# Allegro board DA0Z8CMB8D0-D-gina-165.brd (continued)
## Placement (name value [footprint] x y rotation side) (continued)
HOLE7  *hg-c236d118p2  [HG-C236D118P2]  153.98 171.96 180 bottom
HOLE8  *hg-c236d118p2  [HG-C236D118P2]  145.78 171.46 180 bottom
HOLE9  *hg-c276d118p2  [HG-C276D118P2]  17.5 165.96 180 bottom
HOLE10  *hg-c236d118p2  [HG-C236D118P2]  89.78 157.96 180 bottom
HOLE11  *o-z8c-1  [O-Z8C-1]  230.64 148.36 180 bottom
HOLE12  *h-c217d138p2  [H-C217D138P2]  85.51 142 180 bottom
HOLE13  *hg-c236d118p2  [HG-C236D118P2]  247.2 133.46 180 bottom
HOLE14  *hg-c236d118p2  [HG-C236D118P2]  4.5 132.47 180 bottom
HOLE15  *h-c197d138p2  [H-C197D138P2]  3.5 125.47 180 bottom
HOLE16  *hg-c236d118p2  [HG-C236D118P2]  242.98 103.03 180 bottom
HOLE17  *hg-c276d118p2  [HG-C276D118P2]  188.7 97.46 180 bottom
HOLE18  *h-c236d165p2  [H-C236D165P2]  26.4 92.96 270 bottom
HOLE19  *h-tc197bc142d142p2  [H-TC197BC142D142P2]  194.11 81.96 180 bottom
HOLE20  *hg-c236d118p2  [HG-C236D118P2]  96.2 38.56 180 bottom
HOLE21  *hg-c276d118p2  [HG-C276D118P2]  246.88 26.46 180 bottom
J2  *jump  [JOPEN25X30_S]  127.77 67.07 180 top
JDIM1  ddr3-dimm1_h=5.2_std  [DDR-DS1SK-20401-STD-204P-SMT]  128.03 79.73 0 bottom
L2  blm15bb470sn1d  [RC0402]  103.84 160.64 0 top
L3  blm15bb470sn1d  [RC0402]  105.88 160.64 0 top
L4  blm15bb470sn1d  [RC0402]  107.91 160.64 0 top
L5  hcmc0805-371mfs/0.1a/370ohm  [CHOKE-WCM2012-4P]  138.77 158.48 180 top
L7  hcmc0805-371mfs/0.1a/370ohm  [CHOKE-WCM2012-4P]  138.77 156.32 180 top
L8  80ohm@100mhz  [RC0402]  107.91 155.18 270 top
L9  80ohm@100mhz  [RC0402]  108.8 148.32 270 top
L10  2.2uh/210ma_8  [RC0805]  141.82 143.62 180 top
L11  2.2uh/210ma_8  [RC0805]  141.82 141.59 180 top
L12  2.2uh/210ma_8  [RC0805]  137.5 140.83 90 top
L13  ev@pby160808t-300y-n  [RC0603]  28.28 138.29 270 top
L14  ev@hcb1005kf-181t15(180,1500ma)  [RC0402]  44.54 116.82 270 top
L15  ev@pby160808t-300y-n  [RC0603]  46.36 116.42 0 top
L16  2.2uh/210ma_8  [RC0805]  157.18 113.04 0 top
L17  4.7uh/680ma  [L2_5X1_8-1_8-SMT]  222.84 78.98 0 top
L18  blm11a05s/0.2a/120ohm_6  [RC0402]  140.67 71.23 270 top
L19  blm11a05s/0.2a/120ohm_6  [RC0402]  159.34 56.24 0 top
L20  blm11a05s/0.2a/120ohm_6  [RC0402]  158.84 53.96 0 top
L21  hcb2012kf220t60/6a/22ohm_8  [RC0805]  238.72 51.93 90 top
L23  hcmc0805-371mfs/0.1a/370ohm  [CHOKE-WCM2012-4P]  138.26 157.97 180 bottom
L25  80ohm@100mhz  [RC0402]  109.43 157.21 90 bottom
L26  hcmc0805-371mfs/0.1a/370ohm  [CHOKE-WCM2012-4P]  138.26 155.94 180 bottom
L27  80ohm@100mhz  [RC0402]  98 153.78 180 bottom
L28  80ohm@100mhz  [RC0402]  110.19 147.3 0 bottom
L29  80ohm@100mhz  [RC0402]  98.64 146.67 180 bottom
L30  2.2uh/210ma_8  [RC0805]  144.61 137.02 180 bottom
L31  *0_6  [RC0603]  92.67 50.4 90 bottom
L32  *short_6  [SHORT0603]  93.94 50.4 90 bottom
LED1  power led  [LED19-123-Y2ST1D-C30-2T-4P]  9.8 166.56 270 top
LED2  battery led  [LED19-123-Y2ST1D-C30-2T-4P]  26.3 166.56 270 top
NOREF  -  [unnamed]  30.95 44.43 0 top
NOREF#2  -  [#2]  66.53 163.08 0 top
NOREF#3  -  [#2]  77.81 114.92 0 top
NOREF#4  -  [unnamed]  235.24 150.9 0 top
NOREF#5  -  [#2]  47.77 -35.33 0 top
NOREF#6  -  [unnamed]  13.55 161.78 0 top
NOREF#7  -  [#2]  98.57 5.31 0 top
NOREF#8  -  [#2]  87.33 132.44 180 bottom
NOREF#9  -  [#2]  67.19 164.55 180 bottom
NOREF#10  -  [unnamed]  230.41 28.76 180 bottom
NOREF#11  -  [unnamed]  242.15 134.71 180 bottom
NOREF#12  -  [unnamed]  12.68 119.47 180 bottom
PAD1  *spad-e858x1268  [SPAD-E858X1268]  241.33 116.19 180 bottom
PC1  1500p/50v_4  [CC0402]  151.72 155.3 0 top
PC2  0.33u/6v_4  [CC0402]  147.41 154.92 0 top
PC3  2.2u/10v_4  [CC0402]  147.41 153.91 0 top
PC4  *100p/50v_4  [CC0402]  150.07 153.91 0 top
PC5  0.1u/50v_6  [CC0603]  135.82 151.93 90 top
PC6  1u/6.3v_4  [CC0402]  143.28 151.59 0 top
PC7  *0.1u/25v_4  [CC0402]  152.88 148.92 180 top
PC8  1000p/50v_6  [CC0603]  136.94 148.4 90 top
PC9  *0.1u/25v_4  [CC0402]  152.88 147.73 180 top
PC10  4700p/25v_4  [CC0402]  149.56 145.78 90 top
PC11  1000p/50v_4  [CC0402]  150.71 145.78 90 top
PC12  *ev@2.2n/50v_4  [CC0402]  22.95 141.46 90 top
PC13  *ev@1u/10v_4  [CC0402]  16.14 137.65 90 top
PC14  *ev@680p/50v_6  [CC0603]  11.24 133.9 270 top
PC15  ev@2200p/50v_6  [CC0603]  9.74 126.86 180 top
PC16  ev@4.7u/25v_8  [CC0805]  9.85 124.92 0 top
PC17  ev@0.1u/50v_6  [CC0603]  17.19 122.22 90 top
PC18  ev@1u/10v_4  [CC0402]  18.44 121.92 90 top
PC19  *ev@2.2n/50v_4  [CC0402]  26.12 117.2 0 top
PC20  *ev@1u/10v_4  [CC0402]  26.63 106.03 270 top
PC21  0.1u/50v_6  [CC0603]  30.29 103.82 180 top
PC22  2200p/50v_6  [CC0603]  30.26 102.47 180 top
PC23  ev@0.1u/10v_4  [CC0402]  41.46 99.2 0 top
PC24  0.1u/50v_6  [CC0603]  36.51 98.56 0 top
PC25  ev@10u/6.3v_6  [CC0603]  41.56 97.34 0 top
PC26  ev@10u/6.3v_6  [CC0603]  48.93 94.22 90 top
PC27  ev@1000p/50v_6  [CC0603]  45.65 94.17 180 top
PC28  ev@330u/2v_7343  [CC7343]  53.07 94.01 270 top
PC29  ev@330u/2v_7343  [CC7343]  62.29 93.56 270 top
PC30  ev@1000p/50v_6  [CC0603]  58.56 92.72 180 top
PC31  0.1u/50v_6  [CC0603]  31.71 90.53 90 top
PC32  ev@0.1u/50v_6  [CC0603]  63.59 87.08 90 top
PC33  ev@4.7u/25v_8  [CC0805]  65.36 87 90 top
PC34  ev@4.7u/25v_8  [CC0805]  61.78 86.95 90 top
PC35  0.1u/25v_4  [CC0402]  48.22 80.48 180 top
PC36  ev@0.22u/25v_6  [CC0603]  56.04 80.27 270 top
PC37  *680p/50v_6  [CC0603]  176.79 80.27 180 top
PC38  ev@0.1u/25v_4  [CC0402]  53.13 79.32 180 top
PC39  *ev@1u/10v_4  [CC0402]  67.88 79.05 90 top
PC40  ev@0.22u/25v_6  [CC0603]  49.67 79.05 0 top
PC41  1u/10v_4  [CC0402]  190.46 76.26 180 top
PC42  0.1u/50v_6  [CC0603]  190.25 74.96 180 top
PC43  0.1u/50v_6  [CC0603]  34.14 71.53 0 top
PC44  *ev@0.1u/25v_4  [CC0402]  57.47 70.89 270 top
PC45  ev@2700p/50v_4  [CC0402]  49.11 70.87 270 top
PC46  ev@33p/50v_4  [CC0402]  55.08 70.87 270 top
PC47  ev@1u/6.3v_4  [CC0402]  52.69 70.85 90 top
PC48  2200p/50v_6  [CC0603]  34.16 70.18 180 top
PC49  ev@4700p/25v_4  [CC0402]  54.7 69.17 180 top
PC50  4.7u/25v_8  [CC0805]  35.77 68.56 0 top
PC51  *680p/50v_6  [CC0603]  179.74 68.39 270 top
PC52  4.7u/6.3v_6  [CC0603]  199.09 68.36 180 top
PC53  0.1u/50v_6  [CC0603]  54.46 67.9 180 top
PC54  2200p/50v_6  [CC0603]  36.03 66.91 180 top
PC55  0.1u/50v_6  [CC0603]  52.9 66.58 0 top
PC56  0.1u/50v_6  [CC0603]  193.25 65.49 0 top
PC57  0.1u/50v_6  [CC0603]  201.63 65.31 0 top
PC58  0.47u/25v_6  [CC0603]  54.08 64.4 270 top
PC59  *47p/50v_4  [CC0402]  31.62 63.92 180 top
PC60  0.1u/50v_6  [CC0603]  203.64 63.89 270 top
PC61  0.1u/50v_6  [CC0603]  204.99 63.89 270 top
PC62  *47p/50v_4  [CC0402]  31.6 62.72 180 top
PC63  *680p/50v_6  [CC0603]  47.26 62.56 180 top
PC64  0.1u/25v_4  [CC0402]  195.54 61.45 180 top
PC65  10u/6.3v_6  [CC0603]  198.41 61.45 0 top
PC66  *680p/50v_6  [CC0603]  178.7 60.16 270 top
PC67  0.1u/10v_4  [CC0402]  198.76 59.39 270 top
PC68  0.22u/10v_4  [CC0402]  199.93 59.39 270 top
PC69  0.01u/25v_4  [CC0402]  195.39 59.34 270 top
PC70  0.1u/50v_6  [CC0603]  210.04 59.12 0 top
PC71  0.1u/50v_6  [CC0603]  204.96 57.16 270 top
PC72  1u/10v_4  [CC0402]  193.76 56.75 180 top
PC73  10u/6.3v_6  [CC0603]  201.94 56.14 180 top
PC74  0.1u/50v_6  [CC0603]  193.48 55.48 180 top
PC75  10u/6.3v_6  [CC0603]  201.94 54.87 180 top
PC76  *680p/50v_6  [CC0603]  206.21 54.04 90 top
PC77  0.1u/50v_6  [CC0603]  33.93 52.48 180 top
PC78  2200p/50v_6  [CC0603]  47.08 52.43 0 top
PC79  *100p/50v_4  [CC0402]  31.92 51.56 270 top
PC80  *330u/2v_7343  [CC7343]  171.81 50.66 270 top
PC81  1500p/50v_4  [CC0402]  132.94 49.38 270 top
PC82  *2200p/50v_4  [CC0402]  183.47 46.72 0 top
PC83  0.1u/25v_6  [CC0603]  132.51 43.99 0 top
PC84  *2.2n/50v_4  [CC0402]  206.1 41.77 270 top
PC85  1000p/50v_4  [CC0402]  132.63 41.63 270 top
PC86  22u/6.3v_8  [CC0805]  130.51 153.53 180 bottom
PC87  *330p/50v_4  [CC0402]  151.81 152.96 90 bottom
PC88  *0.01u/50v_4  [CC0402]  152.9 152.96 90 bottom
PC89  4.7u/25v_8  [CC0805]  137.92 152.53 90 bottom
PC90  2200p/50v_4  [CC0402]  136.36 152.51 90 bottom
PC91  0.1u/10v_4  [CC0402]  142.64 152.2 90 bottom
PC92  4.7u/25v_8  [CC0805]  134.07 152 180 bottom
PC93  0.22u/25v_6  [CC0603]  140.67 152 270 bottom
PC94  0.1u/10v_4  [CC0402]  130.06 151.77 180 bottom
PC95  0.12u/10v_4  [CC0402]  152.21 148.02 270 bottom
PC96  1u/10v_4  [CC0402]  141.06 144.89 180 bottom
PC97  ev@330u/2v_7343  [CC7343]  12.66 141.33 90 bottom
PC98  22u/6.3v_8  [CC0805]  128.99 141.21 180 bottom
PC99  *330u/2v_7343  [CC7343]  141.18 140.7 0 bottom
PC100  ev@0.1u/50v_6  [CC0603]  9.57 138.5 90 bottom
PC101  *ev@1u/10v_4  [CC0402]  16.34 115.17 180 bottom
PC102  0.1u/50v_6  [CC0603]  85.56 113.78 180 bottom
PC103  0.1u/50v_6  [CC0603]  93.68 110.85 270 bottom
PC104  ev@0.1u/10v_4  [CC0402]  50.38 100.69 270 bottom
PC105  33u/25v_6x4.5  [ECAP6_3X6_1-7_2]  176.36 100.44 270 bottom
PC106  ev@4.7u/25v_8  [CC0805]  41.97 93.91 90 bottom
PC107  ev@0.1u/50v_6  [CC0603]  39.2 93.43 90 bottom
PC108  ev@10u/25v_8  [CC0805]  62.32 82.03 90 bottom
PC109  ev@10u/25v_8  [CC0805]  67.4 85.84 180 bottom
PC110  330u/2.5v_6x4.2  [ECAP6_3X6_1-7_2]  174.68 83.96 180 bottom
PC111  ev@4.7u/25v_8  [CC0805]  39.56 83.32 180 bottom
PC112  ev@10u/25v_8  [CC0805]  39.56 81.09 0 bottom
PC113  0.1u/50v_6  [CC0603]  168.49 79.49 90 bottom
PC114  ev@33u/25v_6x4.5  [ECAP6_3X6_1-7_2]  66.23 78.04 90 bottom
PC115  ev@10u/25v_8  [CC0805]  44.33 77.56 180 bottom
PC116  *ev@2.2n/50v_4  [CC0402]  78.03 75.44 270 bottom
PC117  4.7u/25v_8  [CC0805]  184.82 74.84 270 bottom
PC118  2200p/50v_6  [CC0603]  186.57 74.69 90 bottom
PC119  *ev@0.1u/25v_4  [CC0402]  54.09 72.83 0 bottom
PC120  2200p/50v_6  [CC0603]  189.82 70.47 0 bottom
PC121  0.1u/50v_6  [CC0603]  52.73 68.7 90 bottom
PC122  4.7u/25v_8  [CC0805]  190.2 68.69 180 bottom
PC123  2200p/50v_6  [CC0603]  205.47 66.4 180 bottom
PC124  100p/50v_4  [CC0402]  59.79 65.98 0 bottom
PC125  47n/50v_6  [CC0603]  51.52 65.17 0 bottom
PC126  4.7u/25v_8  [CC0805]  205.19 64.8 0 bottom
PC127  220u/6.3v_6x4.2  [ECAP6_3X6_1-7_2]  170.5 62.57 0 bottom
PC128  0.1u/50v_6  [CC0603]  178.47 62.57 0 bottom
PC129  1u/16v_6  [CC0603]  51.53 62.46 0 bottom
PC130  0.01u/25v_4  [CC0402]  60.05 61.22 0 bottom
PC131  0.1u/25v_4  [CC0402]  55.58 60.05 90 bottom
PC132  0.1u/25v_4  [CC0402]  60.05 59.42 0 bottom
PC133  0.1u/25v_4  [CC0402]  57.5 58.12 0 bottom
PC134  10u/25v_1206  [CC1206]  55.97 55.86 180 bottom
PC135  10u/6.3v_6  [CC0603]  201.91 54.82 0 bottom
PC136  330u/2.5v_6x4.2  [ECAP6_3X6_1-7_2]  169.17 54.06 90 bottom
PC137  10u/25v_1206  [CC1206]  55.97 53.58 180 bottom
PC138  0.1u/50v_6  [CC0603]  173.59 52.99 270 bottom
PC139  4.7u/25v_8  [CC0805]  184.49 52.36 0 bottom
PC140  2200p/50v_4  [CC0402]  190.08 51.04 0 bottom
PC141  0.1u/50v_6  [CC0603]  204.86 50.83 180 bottom
PC142  *100p/50v_4  [CC0402]  134.18 49.41 90 bottom
PC143  0.01u/25v_4  [CC0402]  136.54 49.36 270 bottom
PC144  33u/25v_6x4.5  [ECAP6_3X6_1-7_2]  179.05 49.31 0 bottom
PC145  10u/6.3v_6  [CC0603]  129.74 47.17 270 bottom
PC146  220u/6.3v_6x4.2  [ECAP6_3X6_1-7_2]  206.26 46.49 0 bottom
PC147  0.1u/10v_4  [CC0402]  146.22 41.83 270 bottom
PC148  10u/6.3v_6  [CC0603]  148.91 41.76 90 bottom
PC149  10u/6.3v_6  [CC0603]  147.49 41.71 90 bottom
PC150  0.1u/50v_6  [CC0603]  134.84 41.12 180 bottom
PD1  1n4148ws  [DSM]  42.48 86.6 90 top
PD2  sbr1045sp5-13  [POWER-6_5-1_84-3P]  39.2 83.68 90 top
PD3  bzt52-b5v6s(5.6v)  [DSM]  31.33 68.69 180 top
PD4  bzt52-b5v6s(5.6v)  [DSM]  31.33 66.79 180 top
PD5  rb500v-40  [DSM]  51.39 62.59 270 top
PD6  1ps302  [UMT_213-3-1_3]  204.3 60.59 270 top
PD7  1ps302  [UMT_213-3-1_3]  207.2 60.16 270 top
PD8  da2j10100l  [DSM]  96.22 99.68 180 bottom
PD9  smaj20a  [D-DO-214AC]  27.62 97.8 180 bottom
PJ1  power conn  [20288-04XX-4P-L]  30.65 100.97 180 bottom
PJ2  50458-00801-v01  [50458-00801-V02-8P-L]  33.38 60.82 270 bottom
PL1  0.15uh_7x7x4  [CHOKE-PCMC063T-R82MN-4P-SMT]  132.29 145.9 180 bottom
PL2  ev@2.2uh_7x7x3  [CHOKE-PCMC063T-3R3MN-SMT]  13.34 132.53 0 bottom
PL3  ev@0.36uh_ldcr  [CHOKE-ETQP4LR36WFC-4P]  51.19 92.29 270 bottom
PL4  ev@0.36uh_ldcr  [CHOKE-ETQP4LR36WFC-4P]  62.67 92.14 270 bottom
PL5  2.2uh_7x7x3  [CHOKE-PCMC063T-3R3MN-SMT]  173.85 76.41 180 bottom
PL6  2.2uh_7x7x3  [CHOKE-PCMC063T-3R3MN-SMT]  179.16 66.91 180 bottom
PL7  6.8uh_7x7x3  [CHOKE-PCMC063T-3R3MN-SMT]  46.69 61.35 90 bottom
PL8  0.68uh_7x7x3  [CHOKE-PCMC063T-3R3MN-SMT]  181.06 57.39 180 bottom
PL9  2.2uh_7x7x3  [CHOKE-PCMC063T-3R3MN-SMT]  208.77 55.33 90 bottom
PL10  1uh_7x7x3  [CHOKE-PCMC063T-3R3MN-SMT]  140.99 43.99 0 bottom
PQ1  ev@pdtc143tt  [SOT23_213-3_3-2]  11.46 142.78 180 top
PQ2  ev@2n7002k  [SOT23_213-3_3-2]  15.71 140.57 180 top
PQ3  ev@2n7002k  [SOT23_213-3_3-2]  19.9 138.16 270 top
PQ4  ev@aon7408  [WDFN5-3_05X3_05-65]  24.09 138.16 90 top
PQ5  ev@ao3404  [SOT23_213-3_3-2]  25.23 114.66 270 top
PQ6  ev@2n7002k  [SOT23_213-3_3-2]  28.91 113.14 270 top
PQ7  ev@pdtc143tt  [SOT23_213-3_3-2]  27.9 109.08 270 top
PQ8  ev@2n7002k  [SOT23_213-3_3-2]  31.48 109.08 270 top
PQ9  aol1413  [SO-8FL-5P-OA]  38.62 92.29 180 top
PQ10  *ev@rjk03k5dpa  [SO-8FL-5P-OA]  78.52 89.57 90 top
PQ11  imd2at108  [IMD]  31.07 85.33 180 top
PQ12  ev@aon6414al  [SO-8FL-5P-OA]  63.05 81.98 180 top
PQ13  2n7002dw  [SC70-2_1-65-6P]  44.91 78.53 0 top
PQ14  *ev@pdtc143tt  [SOT23_213-3_3-2]  71.84 76.95 270 top
PQ15  ev@2n7002k  [SOT23_213-3_3-2]  59.96 72.49 90 top
PQ16  2n7002k  [SOT23_213-3_3-2]  175.47 71.18 0 top
PQ17  aon7410  [WDFN5-3_05X3_05-65]  39.95 69.93 0 top
PQ18  2n7002k  [SOT23_213-3_3-2]  59.18 67.94 0 top
PQ19  2n7002k  [SOT23_213-3_3-2]  175.29 67.24 0 top
PQ20  2n7002k  [SOT23_213-3_3-2]  35.12 64.13 180 top
PQ21  *2n7002k  [SOT23_213-3_3-2]  59.05 62.01 180 top
PQ22  aol1413  [SO-8FL-5P-OA]  38.97 56.54 90 top
PQ23  dtc144eu  [UMT_213-3-1_3]  180.63 51.42 90 top
PQ24  2n7002k  [SOT23_213-3_3-2]  209.25 49.64 180 top
PQ25  2n7002k  [SOT23_213-3_3-2]  180.3 47.74 180 top
PQ26  dtc144eu  [UMT_213-3-1_3]  205.9 47 90 top
PQ27  2n7002k  [SOT23_213-3_3-2]  209.38 45.83 180 top
PQ28  *2n7002k  [SOT23_213-3_3-2]  138.31 44.84 180 top
PQ29  2n7002k  [SOT23_213-3_3-2]  203.69 42.58 270 top
PQ30  ev@aon7752  [WDFN5-3_05X3_05-65]  16.91 125.26 270 bottom
PQ31  ev@aon7410  [WDFN5-3_05X3_05-65]  10.87 124.77 0 bottom
PQ32  aon7408  [WDFN5-3_05X3_05-65]  161.95 114.07 180 bottom
PQ33  2n7002k  [SOT23_213-3_3-2]  163.53 106.41 270 bottom
PQ34  2n7002k  [SOT23_213-3_3-2]  88.35 103.49 0 bottom
PQ35  2n7002k  [SOT23_213-3_3-2]  95.72 103.36 90 bottom
PQ36  ao3409  [SOT23_213-3_3-2]  99.4 103.36 270 bottom
PQ37  dtc144eu  [UMT_213-3-1_3]  102.7 102.6 270 bottom
PQ38  ev@aon6414al  [SO-8FL-5P-OA]  41.06 88.86 0 bottom
PQ39  ev@aon6752  [SO-8FL-5P-OA]  56.98 84.06 270 bottom
PQ40  ev@aon6752  [SO-8FL-5P-OA]  46.95 81.64 0 bottom
PQ41  aon7752  [WDFN5-3_05X3_05-65]  181.01 77.25 0 bottom
PQ42  *ev@2n7002k  [SOT23_213-3_3-2]  75.78 77.2 270 top
PQ43  *ev@2n7002k  [SOT23_213-3_3-2]  71.84 76.95 270 bottom
PQ44  aon7410  [WDFN5-3_05X3_05-65]  180.65 72.75 90 bottom
PQ45  ao3404  [SOT23_213-3_3-2]  167.14 72.45 180 bottom
PQ46  aon7410  [WDFN5-3_05X3_05-65]  186.09 69.4 180 bottom
PQ47  ao3404  [SOT23_213-3_3-2]  167.14 68.61 180 bottom
PQ48  aon7410  [WDFN5-3_05X3_05-65]  44.92 68.31 0 bottom
PQ49  aon7752  [WDFN5-3_05X3_05-65]  186.27 64.91 0 bottom
PQ50  aon7410  [WDFN5-3_05X3_05-65]  209.74 62.47 180 bottom
PQ51  aon7752  [WDFN5-3_05X3_05-65]  204 61.55 180 bottom
PQ52  aon6970  [POWER-5X6-1_27-7P]  188.93 55.18 270 bottom
PQ53  aon7408  [WDFN5-3_05X3_05-65]  213.95 48.75 0 bottom
PQ54  *ao3404  [SOT23_213-3_3-2]  151.85 46.72 270 bottom
PQ55  aon7408  [WDFN5-3_05X3_05-65]  213.88 43.65 0 bottom
PR1  4.75k/f_4  [RC0402]  149.69 155.3 180 top
PR2  *75/f_4  [RC0402]  144.36 154.42 90 top
PR3  56_4  [RC0402]  145.63 154.42 90 top
PR4  *short_4  [SHORT0402]  152.88 153.31 90 top
PR5  *short_4  [SHORT0402]  151.68 153.29 90 top
PR6  130/f_4  [RC0402]  143.3 152.65 180 top
PR7  *0_4  [RC0402]  143.35 150.34 0 top
PR8  *short_4  [SHORT0402]  152.88 150.11 0 top
PR9  *0_4  [RC0402]  143.5 149.12 180 top
PR10  2.2_6  [RC0603]  135.57 148.37 270 top
PR11  *short_4  [SHORT0402]  143.5 147.93 0 top
PR12  2.26k/f_4  [RC0402]  132.88 146.11 90 top
PR13  *short_4  [SHORT0402]  131.68 146.08 270 top
PR14  *90.9k/f_4  [RC0402]  147.09 145.82 270 top
PR15  20k/f_4  [RC0402]  144.65 145.8 90 top
PR16  100k/f_4  [RC0402]  145.87 145.8 90 top
PR17  2m/f_4  [RC0402]  148.29 145.78 270 top
PR18  *100k/f_4  [RC0402]  143.45 145.77 90 top
PR19  10k/f_4  [RC0402]  151.96 145.77 270 top
PR20  30k/f_4  [RC0402]  148.8 144.26 180 top
PR21  *short_8  [SHORT0805]  138.13 143.62 180 top
PR22  2m/f_4  [RC0402]  148.8 143.24 0 top
PR23  ev@22_8  [RC0805]  19.52 141.46 0 top
PR24  ev@1m_4  [RC0402]  21.93 141.46 90 top
PR25  ev@1m_4  [RC0402]  10.5 140.17 0 top
PR26  ev@1m_4  [RC0402]  12.58 140.17 0 top
PR27  ev@100k_4  [RC0402]  14.69 137.65 270 top
PR28  *ev@short_4  [SHORT0402]  17.15 137.65 270 top
PR29  *ev@4.7_6  [RC0603]  11.2 131.11 270 top
PR30  *ev@short_6  [SHORT0603]  15.84 122.2 90 top
PR31  ev@1m_4  [RC0402]  23.96 117.2 180 top
PR32  ev@470k/f_4  [RC0402]  20.41 116.95 90 top
PR33  ev@100k/f_4  [RC0402]  14.56 116.06 270 top
PR34  *ev@short_4  [SHORT0402]  18.38 115.11 180 top
PR35  ev@100k/f_4  [RC0402]  16.34 115.05 180 top
PR36  ev@100k_4  [RC0402]  27.9 106.03 90 top
PR37  *ev@short_4  [SHORT0402]  29.17 106.03 90 top
PR38  ev@1m_4  [RC0402]  30.57 106.03 90 top
PR39  ev@1m_4  [RC0402]  31.71 106.03 270 top
PR40  ev@22_8  [RC0805]  34.12 106.03 0 top
PR41  ev@2.2_6  [RC0603]  45.65 92.8 180 top
PR42  ev@2.2_6  [RC0603]  57.84 90.64 270 top
PR43  220k_4  [RC0402]  33.11 90.28 90 top
PR44  *short_4  [SHORT0402]  30.18 88.12 90 top
PR45  220k_4  [RC0402]  31.2 88.12 270 top
PR46  ev@10k/f_4  [RC0402]  44.31 87.44 90 top
PR47  ev@10k/f_4  [RC0402]  57.49 82.71 90 top
PR48  *short_6  [SHORT0603]  43.27 82.41 270 top
PR49  100k_4  [RC0402]  45.64 80.37 180 top
PR50  ev@2.2/f_6  [RC0603]  57.44 80.27 270 top
PR51  *ev@1m_4  [RC0402]  70.62 79.59 0 top
PR52  *ev@1m_4  [RC0402]  72.86 79.59 0 top
PR53  *4.7_6  [RC0603]  174.74 79.44 270 top
PR54  *short_4  [SHORT0402]  42.26 78.49 270 top
PR55  100k_4  [RC0402]  47.48 78.39 270 top
PR56  ev@2.2/f_6  [RC0603]  49.67 77.68 0 top
PR57  *ev@short_4  [SHORT0402]  58.86 77.5 0 top
PR58  *0_4  [RC0402]  43.5 76.78 180 top
PR59  *10k_4  [RC0402]  45.84 76.78 180 top
PR60  *ev@0_4  [RC0402]  67.88 77.02 90 top
PR61  5.1k/f_4  [RC0402]  198.54 76.62 180 top
PR62  ev@10k/f_4  [RC0402]  58.86 76.33 180 top
PR63  10k/f_4  [RC0402]  198.54 75.45 180 top
PR64  ev@10k_4  [RC0402]  61.11 75.16 0 top
PR65  ev@10k/f_4  [RC0402]  58.86 75.14 180 top
PR66  *ev@10k_4  [RC0402]  49.29 74.96 0 top
PR67  *ev@100k_4  [RC0402]  67.88 74.99 90 top
PR68  105k/f_4  [RC0402]  198.54 74.28 0 top
PR69  0.02/f_0612  [RC3216]  39.97 74.01 0 top
PR70  ev@100k_4  [RC0402]  49.29 73.77 180 top
PR71  *short_6  [SHORT0603]  190.18 73.54 180 top
PR72  *100k/f_4  [RC0402]  198.56 73.14 180 top
PR73  20_1206  [RC1206]  46.78 72.95 90 top
PR74  *ev@short_4  [SHORT0402]  49.29 72.55 180 top
PR75  ev@16.2k/f_4  [RC0402]  56.3 70.92 270 top
PR76  ev@20k/f_4  [RC0402]  50.3 70.87 270 top
PR77  ev@20k/f_4  [RC0402]  51.5 70.87 90 top
PR78  ev@1k/f_4  [RC0402]  53.89 70.87 270 top
PR79  22_8  [RC0805]  171.59 69.15 180 top
PR80  6.81k/f_4  [RC0402]  195.28 68.18 180 top
PR81  *100k_4  [RC0402]  56.45 68.06 270 top
PR82  84.5k/f_4  [RC0402]  201.61 67.78 0 top
PR83  *4.7_6  [RC0603]  182.05 67.6 0 top
PR84  22_8  [RC0805]  171.18 66.76 180 top
PR85  *100k/f_4  [RC0402]  193.53 66.74 180 top
PR86  *short_6  [SHORT0603]  201.63 66.63 180 top
PR87  100_4  [RC0402]  31.65 65.13 180 top
PR88  127k/f_4  [RC0402]  57.87 65.01 270 top
PR89  *0_4  [RC0402]  59.27 65.01 90 top
PR90  *short_4  [SHORT0402]  60.41 65.01 270 top
PR91  1/f_6  [RC0603]  193.25 64.2 0 top
PR92  1/f_6  [RC0603]  201.63 64.09 0 top
PR93  *4.7_6  [RC0603]  44.88 63.32 90 top
PR94  10k_4  [RC0402]  55.84 62.72 0 top
PR95  33k/f_4  [RC0402]  37.3 61.83 0 top
PR96  100_4  [RC0402]  31.59 61.51 180 top
PR97  316k/f_4  [RC0402]  55.78 60.79 0 top
PR98  100_4  [RC0402]  31.58 60.19 180 top
PR99  30.1k/f_4  [RC0402]  197.06 60 180 top
PR100  10k_4  [RC0402]  35.14 59.93 270 top
PR101  1m_4  [RC0402]  33.68 59.84 90 top
PR102  *100k_4  [RC0402]  58.19 59.47 0 top
PR103  *short_4  [SHORT0402]  31.57 59.1 180 top
PR104  10k/f_4  [RC0402]  197.06 58.84 0 top
PR105  *4.7_6  [RC0603]  179.46 58.02 0 top
PR106  *4.7_6  [RC0603]  206.97 56.35 0 top
PR107  22_8  [RC0805]  210.7 55.46 270 top
PR108  2/f_6  [RC0603]  193.43 54.06 0 top
PR109  *100k/f_6  [RC0603]  182.84 52.05 90 top
PR110  *0_4  [RC0402]  196.1 51.37 270 top
PR111  *short_4  [SHORT0402]  194.98 51.34 90 top
PR112  15.4k/f_4  [RC0402]  197.24 51.34 270 top
PR113  200k/f_4  [RC0402]  198.38 51.32 270 top
PR114  *100k/f_4  [RC0402]  199.53 51.32 90 top
PR115  1m_4  [RC0402]  182.97 49.51 90 top
PR116  8.06k/f_4  [RC0402]  134.16 49.4 270 top
PR117  22_8  [RC0805]  212.94 49.13 0 top
PR118  1m_4  [RC0402]  183.47 47.86 0 top
PR119  1m_4  [RC0402]  177.63 47.74 90 top
PR120  22_8  [RC0805]  213.19 45.58 0 top
PR121  *1m_6  [RC0603]  199.83 45.09 270 top
PR122  1m_6  [RC0603]  201.18 45.09 90 top
PR123  *22_8  [RC0805]  142.27 44.84 0 top
PR124  1m_6  [RC0603]  199.78 42.2 90 top
PR125  1m_6  [RC0603]  201.23 42.17 270 top
PR126  4.75k/f_4  [RC0402]  150.07 155.56 180 bottom
PR127  *10_4  [RC0402]  151.72 155.41 270 bottom
PR128  *10_4  [RC0402]  152.74 155.41 90 bottom
PR129  *56_4  [RC0402]  145.63 154.42 90 bottom
PR130  *short_4  [SHORT0402]  142.2 154.67 0 bottom
PR131  10k/f_4  [RC0402]  150.07 154.03 0 bottom
PR132  20/f_6  [RC0603]  147.66 153.96 180 bottom
PR133  1_6  [RC0603]  143.9 152.13 270 bottom
PR134  2.2/f_6  [RC0603]  139.51 152 90 bottom
PR135  *short_8  [SHORT0805]  150.2 151.24 90 bottom
PR136  *100k/f_4  [RC0402]  143.5 150.22 0 bottom
PR137  150k/f_4  [RC0402]  146.1 149.17 270 bottom
PR138  *short_4  [SHORT0402]  150.12 148.5 270 bottom
PR139  348k/f_4  [RC0402]  147.95 148.28 0 bottom
PR140  16.9k/f_4  [RC0402]  153.4 148.04 270 bottom
PR141  100k/f_4  [RC0402]  143.5 147.93 180 bottom
PR142  665k/f_4  [RC0402]  145.87 145.8 270 bottom
PR143  150k/f_4  [RC0402]  147.11 145.8 90 bottom
PR144  36.5k/f_4  [RC0402]  144.65 145.8 270 bottom
PR145  39k/f_4  [RC0402]  148.31 145.8 90 bottom
PR146  9.09k/f_4  [RC0402]  149.65 145.8 270 bottom
PR147  100k/f_4_4250ntc  [RC0402]  143.47 145.78 90 bottom
PR148  *39.2k/f_4  [RC0402]  151.96 145.77 270 bottom
PR149  39k/f_4  [RC0402]  150.73 145.7 90 bottom
PR150  10k/f_4_3435kntc  [RC0402]  131.66 141.21 90 bottom
PR151  2.94k/f_4  [RC0402]  132.8 141.21 90 bottom
PR152  200k_6  [RC0603]  92.54 120.76 180 bottom
PR153  ev@10k/f_4  [RC0402]  17.36 116.82 270 bottom
PR154  ev@9.31k/f_4  [RC0402]  15.55 116.47 180 bottom
PR155  200k/f_4  [RC0402]  98.76 114.72 180 bottom
PR156  *short_6  [SHORT0603]  85.56 112.38 180 bottom
PR157  10k/f_4_3435ntc  [RC0402]  95.08 110.85 270 bottom
PR158  1.33k/f_4  [RC0402]  96.35 110.85 270 bottom
PR159  200k/f_4  [RC0402]  97.62 110.85 270 bottom
PR160  22_8  [RC0805]  163.53 109.46 180 bottom
PR161  1m_6  [RC0603]  100.92 99.68 180 bottom
PR162  *ev@22_8  [RC0805]  70.82 80.76 90 bottom
PR163  *ev@1m_4  [RC0402]  72.96 79.61 180 bottom
PR164  ev@2.2_6  [RC0603]  52.95 77.09 0 bottom
PR165  470k/f_4  [RC0402]  198.51 76.62 0 bottom
PR166  ev@0_4  [RC0402]  49.36 76.31 0 bottom
PR167  ev@10k_4  [RC0402]  58.87 76.17 180 bottom
PR168  *ev@1.33k/f_4  [RC0402]  56.03 75.16 270 bottom
PR169  ev@100k/f_4_4250ntc  [RC0402]  58.87 75.01 180 bottom
PR170  *ev@0_4  [RC0402]  49.29 74.96 0 bottom
PR171  *0_4  [RC0402]  198.54 74.28 0 bottom
PR172  *100k/f_4  [RC0402]  196.22 73.9 270 bottom
PR173  ev@15.8k/f_4  [RC0402]  58.9 73.81 180 bottom
PR174  *ev@short_4  [SHORT0402]  49.29 73.77 180 bottom
PR175  *short_4  [SHORT0402]  198.59 73.14 180 bottom
PR176  ev@100_4  [RC0402]  56.03 73 90 bottom
PR177  ev@66.5k/f_4  [RC0402]  51.88 72.85 0 bottom
PR178  *ev@1k/f_4  [RC0402]  49.29 72.57 0 bottom
PR179  *ev@short_4  [SHORT0402]  58.06 71.83 180 bottom
PR180  ev@0_4  [RC0402]  49.11 70.87 270 bottom
PR181  ev@18k/f_4  [RC0402]  50.3 70.87 90 bottom
PR182  ev@2k/f_4  [RC0402]  51.5 70.87 270 bottom
PR183  ev@100_4  [RC0402]  56.05 70.79 90 bottom
PR184  ev@5.1k/f_4  [RC0402]  53.23 70.71 0 bottom
PR185  *ev@short_4  [SHORT0402]  58.01 70.48 180 bottom
PR186  15.4k/f_4  [RC0402]  197.32 69.33 0 bottom
PR187  10k/f_4  [RC0402]  199.48 69.33 180 bottom
PR188  *short_4  [SHORT0402]  50.95 69.28 180 bottom
PR189  63.4k/f_4  [RC0402]  59.85 68.39 180 bottom
PR190  10k/f_4  [RC0402]  195.28 68.18 0 bottom
PR191  10k/f_4  [RC0402]  198.46 68.18 180 bottom
PR192  *short_4  [SHORT0402]  50.95 68.11 180 bottom
PR193  10k_4  [RC0402]  55.51 68.03 270 bottom
PR194  100k_4  [RC0402]  56.71 68.03 90 bottom
PR195  69.8k/f_4  [RC0402]  193.63 67.29 90 bottom
PR196  10k/f_4  [RC0402]  59.82 67.2 0 bottom
PR197  *short_4  [SHORT0402]  196.55 67.04 180 bottom
PR198  *short_6  [SHORT0603]  199.86 66.15 0 bottom
PR199  *short_4  [SHORT0402]  193.51 65.64 180 bottom
PR200  *short_4  [SHORT0402]  59.78 64.81 180 bottom
PR201  *short_6  [SHORT0603]  51.52 63.82 180 bottom
PR202  *short_4  [SHORT0402]  59.83 63.57 180 bottom
PR203  100k/f_4  [RC0402]  59.83 62.39 0 bottom
PR204  *short_6  [SHORT0603]  195.28 61.43 180 bottom
PR205  7.5_6  [RC0603]  58.24 60.12 270 bottom
PR206  10/f_6  [RC0603]  56.86 60.11 270 bottom
PR207  0.01/f_0612  [RC3216]  52.03 58.66 180 bottom
PR208  *short_4  [SHORT0402]  55.25 58.53 180 bottom
PR209  *short_4  [SHORT0402]  55.25 57.51 180 bottom
PR210  *short_6  [SHORT0603]  197.65 56.91 180 bottom
PR211  *0_4  [RC0402]  196.71 53.53 180 bottom
PR212  *short_4  [SHORT0402]  195.79 51.95 0 bottom
PR213  113k/f_4  [RC0402]  131.74 49.38 270 bottom
PR214  100k/f_4  [RC0402]  132.96 49.38 90 bottom
PR215  121k/f_4  [RC0402]  135.34 49.38 270 bottom
PR216  *short_6  [SHORT0603]  134.84 42.44 0 bottom
PR217  *100k/f_4  [RC0402]  132.65 41.56 90 bottom
PR218  *short_4  [SHORT0402]  131.48 41.53 270 bottom
PU1  tps51624rsm  [QFN32-4X4-4-42P-1H]  148.03 150.27 270 top
PU2  ev@tps51211dscr  [SON10-3X3-5-16P]  17.37 118.04 0 top
PU3  ev@ up1642rqag  [QFN24-4X4-5-25P]  53.91 75.06 270 top
PU4  tps51211dscr  [SON10-3X3-5-16P]  194.65 74.41 90 top
PU5  tps51225rukr  [QFN20-3X3-4-26P]  197.42 65.24 180 top
PU6  tps51216rukr  [QFN20-3X3-4-26P]  197.7 55.41 90 top
PU7  csd97374cq4m  [SON8-4_5X3_5-5-9P-SMT]  139.53 148.07 180 bottom
PU8  ba10393f  [SOIC8-6-1_27]  92.34 117.2 270 bottom
PU9  bq24737rgrr  [PVQFN20-3_5X3_5-5-25P]  55.74 64.39 0 bottom
PU10  tps54318rter  [QFN16-3X3-5-22P]  133.01 45.6 90 bottom
Q1  2n7002k  [SOT23_213-3_3-2]  77.3 154.29 270 top
Q2  2n7002k  [SOT23_213-3_3-2]  81.11 154.29 270 top
Q3  bsn20  [SOT23_213-3_3-2]  84.79 152.51 270 top
Q4  ev@metr3904-g  [SOT23_213-3_3-2]  20.84 148.05 180 top
Q5  ev@dtc144eu  [UMT_213-3-1_3]  13.8 146.54 270 top
Q6  ev@mmbt3904-7-f  [SOT23_213-3_3-2]  16.98 146.54 270 top
Q7  ev@dtc144eua  [UMT_213-3-1_3]  20.91 144.76 180 top
Q8  fdv301n  [SOT23_213-3_3-2]  93.68 132.44 270 top
Q9  mmbt3904-7-f  [SOT23_213-3_3-2]  97.49 132.44 270 top
Q10  ev@2n7002k  [SOT23_213-3_3-2]  52.54 117.71 0 top
Q11  ev@2n7002k  [SOT23_213-3_3-2]  29.3 117.08 0 top
Q12  ev@2n7002dw  [SC70-2_1-65-6P]  63.33 114.79 180 top
Q13  *evg@2n7002k  [SOT23_213-3_3-2]  32.6 113.14 270 top
Q14  *evg@2n7002k  [SOT23_213-3_3-2]  36.28 113.14 90 top
Q15  ev@2n7002k  [SOT23_213-3_3-2]  41.49 109.2 90 top
Q16  dtc144eu  [UMT_213-3-1_3]  60.28 107.3 0 top
Q17  *tpl@2n7002k  [SOT23_213-3_3-2]  77.71 106.84 0 top
Q18  2n7002dw  [SC70-2_1-65-6P]  64.35 104.25 180 top
Q19  *2n7002dw  [SC70-2_1-65-6P]  145.94 94.72 90 top
Q20  2n7002dw  [SC70-2_1-65-6P]  149.88 94.72 90 top
Q21  2n7002dw  [SC70-2_1-65-6P]  200.11 92.82 270 top
Q22  2n7002dw  [SC70-2_1-65-6P]  205.95 92.69 270 top
Q23  *ao3413  [SOT23_213-3_3-2]  145.5 87.99 0 top
Q24  *2n7002k  [SOT23_213-3_3-2]  153.76 87.99 0 top
Q25  2n7002k  [SOT23_213-3_3-2]  90.64 85.33 90 top
Q26  *2n7002k  [SOT23_213-3_3-2]  209.38 74.91 270 top
Q27  *dtc144eu  [UMT_213-3-1_3]  213.32 74.15 0 top
Q28  ao3413  [SOT23_213-3_3-2]  215.6 66.53 270 top
Q29  2n7002k  [SOT23_213-3_3-2]  132.8 53.96 90 top
Q30  *2n7002k  [SOT23_213-3_3-2]  162.52 53.96 0 top
Q31  kbl@dtc144eu  [UMT_213-3-1_3]  69.3 49.64 180 top
Q32  kbl@ao3413  [SOT23_213-3_3-2]  73.24 48.24 270 top
Q33  *mmbt3904-7-f  [SOT23_213-3_3-2]  148.68 42.4 180 top
Q34  *dtc144eu  [UMT_213-3-1_3]  152.74 42.4 180 top
Q35  ev@mmbt3904-7-f  [SOT23_213-3_3-2]  11.64 158.23 270 bottom
Q36  ap2331sa-7  [SOT23_213-3_3-2]  112.35 158.23 180 bottom
Q37  ap2331sa-7  [SOT23_213-3_3-2]  83.91 156.83 90 bottom
Q38  bsn20  [SOT23_213-3_3-2]  84.79 152.51 270 bottom
Q39  *2n7002k  [SOT23_213-3_3-2]  99.02 130.54 270 bottom
Q40  mmbt3904-7-f  [SOT23_213-3_3-2]  182.46 81.77 270 bottom
Q41  ao3413  [SOT23_213-3_3-2]  215.6 65.13 270 bottom
Q42  *mmbt3904  [UMT_213-3-1_3]  84.15 75.1 0 top
R1  *short_4  [SHORT0402]  150.58 164.19 0 top
R2  *short_4  [SHORT0402]  150.58 163.18 0 top
R3  2.2k_4  [RC0402]  114.64 161.15 90 top
R4  ev@100/f_4  [RC0402]  59.01 160.64 270 top
R5  ev@100/f_4  [RC0402]  60.16 160.64 90 top
R6  75_4  [RC0402]  149.82 160.64 90 top
R7  75_4  [RC0402]  149.69 158.99 180 top
R8  ev@243_4  [RC0402]  31 158.97 0 top
R9  ev@100/f_4  [RC0402]  61.22 158.84 90 top
R10  ev@100/f_4  [RC0402]  62.37 158.84 270 top
R11  75/f_4  [RC0402]  103.84 158.61 0 top
R12  75/f_4  [RC0402]  105.88 158.61 0 top
R13  75/f_4  [RC0402]  107.91 158.61 0 top
R14  *short_4  [SHORT0402]  84.79 158.35 270 top
R15  ev@100/f_4  [RC0402]  63.51 158.33 270 top
R16  ev@100/f_4  [RC0402]  64.65 158.33 90 top
R17  ev@100/f_4  [RC0402]  65.8 158.33 270 top
R18  ev@100/f_4  [RC0402]  66.94 158.33 90 top
R19  470_4  [RC0402]  72.86 158.23 90 top
R20  470_4  [RC0402]  74 158.23 90 top
R21  470_4  [RC0402]  75.27 158.23 90 top
R22  470_4  [RC0402]  76.41 158.23 90 top
R23  470_4  [RC0402]  77.68 158.23 90 top
R24  470_4  [RC0402]  78.83 158.23 90 top
R25  470_4  [RC0402]  80.22 158.23 90 top
R26  470_4  [RC0402]  81.37 158.23 90 top
R27  *short_4  [SHORT0402]  149.95 157.84 0 top
R28  ev@1.33k/f_4  [RC0402]  31 157.83 0 top
R29  *short_4  [SHORT0402]  149.95 156.83 0 top
R30  ev@1.33k/f_4  [RC0402]  31 156.68 180 top
R31  300_4  [RC0402]  10.37 156.45 270 top
R32  680_4  [RC0402]  11.52 156.45 270 top
R33  10k_4  [RC0402]  126.2 156.45 180 top
R34  ev@10k/f_4  [RC0402]  57.79 156.3 270 top
R35  ev@100/f_4  [RC0402]  58.94 156.3 270 top
R36  ev@100/f_4  [RC0402]  62.87 156.05 0 top
R37  20k_4  [RC0402]  83.52 155.69 90 top
R38  ev@100/f_4  [RC0402]  61.25 155.67 90 top
R39  ev@100/f_4  [RC0402]  69.94 154.54 270 top
R40  *100k/f_4  [RC0402]  74.76 154.54 90 top
R41  ev@100/f_4  [RC0402]  67.32 154.52 270 top
R42  ev@100/f_4  [RC0402]  68.46 154.52 270 top
R43  ev@243_4  [RC0402]  31 154.4 0 top
R44  *1m_4  [RC0402]  10.37 154.16 90 top
R45  *1m_4  [RC0402]  11.52 154.16 90 top
R46  ev@243_4  [RC0402]  56.6 154.16 90 top
R47  ev@10k/f_4  [RC0402]  57.79 154.14 270 top
R48  ev@100/f_4  [RC0402]  58.94 154.14 90 top
R49  ev@100/f_4  [RC0402]  65.8 154.02 180 top
R50  2.2k_4  [RC0402]  87.33 152.64 90 top
R51  ev@100/f_4  [RC0402]  66.05 152.24 270 top
R52  ev@100/f_4  [RC0402]  67.32 152.24 270 top
R53  ev@100/f_4  [RC0402]  68.46 152.24 270 top
R54  ev@100/f_4  [RC0402]  69.99 152.24 270 top
R55  1m_4  [RC0402]  81.87 151.75 180 top
R56  ev@4.7k_4  [RC0402]  21.85 150.71 180 top
R57  *short_4  [SHORT0402]  87.33 150.61 90 top
R58  ev@100/f_4  [RC0402]  64.4 150.46 0 top
R59  ev@4.7k_4  [RC0402]  23.45 150.22 270 top
R60  2.2k_4  [RC0402]  84.16 149.84 0 top
R61  ev@10k/f_4  [RC0402]  66.68 149.83 270 top
R62  ev@243_4  [RC0402]  67.83 149.83 270 top
R63  ev@100/f_4  [RC0402]  64.4 149.32 180 top
R64  ev@4.7k_4  [RC0402]  11.18 146.62 0 top
R65  ev@4.7k_4  [RC0402]  23.45 145.91 270 top
R66  *ev@100k/f_4  [RC0402]  11.21 145.5 180 top
R67  ev@0_6  [RC0603]  27.26 144.89 270 top
R68  ev@162_4  [RC0402]  44.92 143.87 0 top
R69  ev@100k/f_4  [RC0402]  23.45 143.75 270 top
R70  ev@1.5k/f_4  [RC0402]  14.06 143.49 90 top
R71  ev@4.7k_4  [RC0402]  16.72 142.99 180 top
R72  *short_4  [SHORT0402]  234.53 142.73 270 top
R73  *short_4  [SHORT0402]  235.54 142.73 270 top
R74  8m4m@15_4  [RC0402]  151.6 140.57 180 top
R75  8m@15_4  [RC0402]  153.76 140.57 0 top
R76  *10k_4  [RC0402]  155.41 139.94 90 top
R77  *1k_4  [RC0402]  151.6 139.43 180 top
R78  8m4m@15_4  [RC0402]  153.76 139.43 0 top
R79  *short_6  [SHORT0603]  144.87 139.28 0 top
R80  10k_4  [RC0402]  149.56 138.67 90 top
R81  *short_4  [SHORT0402]  110.96 138.03 270 top
R82  *short_4  [SHORT0402]  112.1 138.03 270 top
R83  *ev@200/f_4  [RC0402]  29.42 137.4 90 top
R84  *short_6  [SHORT0603]  136.1 137.14 0 top
R85  *8m@short_4  [SHORT0402]  148.68 137.02 180 top
R86  100k_4  [RC0402]  148.68 136 0 top
R87  ev@162_4  [RC0402]  55.58 135.62 90 top
R88  *10k_4  [RC0402]  148.68 134.98 0 top
R89  10k_4  [RC0402]  148.68 133.97 180 top
R90  *10k_4  [RC0402]  82.64 132.95 0 top
R91  10k_4  [RC0402]  148.68 132.95 180 top
R92  10k_4  [RC0402]  148.68 131.94 180 top
R93  *1k_4  [RC0402]  157.57 130.67 180 top
R94  10k_4  [RC0402]  148.68 129.9 180 top
R95  1k_4  [RC0402]  95.46 129.78 180 top
R96  1k_4  [RC0402]  98.13 129.78 180 top
R97  10k_4  [RC0402]  156.8 129.52 0 top
R98  10k_4  [RC0402]  148.68 128.89 180 top
R99  *1k_4  [RC0402]  156.8 128.51 180 top
R100  8m@15_4  [RC0402]  150.83 128 180 top
R101  iv@10k_4  [RC0402]  148.68 127.87 0 top
R102  8m@15_4  [RC0402]  152.49 127.49 270 top
R103  51_4  [RC0402]  97.88 126.98 0 top
R104  ev@10k_4  [RC0402]  148.68 126.86 0 top
R105  8m4m@15_4  [RC0402]  153.63 126.73 270 top
R106  *1k_4  [RC0402]  154.64 126.73 90 top
R107  24.9/f_4  [RC0402]  132.27 126.6 180 top
R108  10k_4  [RC0402]  150.33 126.48 90 top
R109  150_6  [RC0603]  97.88 125.84 180 top
R110  10k_4  [RC0402]  148.68 125.84 180 top
R111  8m4m@15_4  [RC0402]  151.34 125.33 90 top
R112  8m4m@15_4  [RC0402]  152.49 125.33 90 top
R113  *short_6  [SHORT0603]  154.42 124.95 0 top
R114  10k_4  [RC0402]  148.68 124.82 180 top
R115  10k_4  [RC0402]  150.33 124.44 90 top
R116  ev@10k/f_4  [RC0402]  28.33 124.43 0 top
R117  *short_8  [SHORT0805]  161.45 124.19 270 top
R118  *10k_4  [RC0402]  148.68 123.81 180 top
R119  *0_4  [RC0402]  129.88 123.05 180 top
R120  *10k_4  [RC0402]  148.68 122.79 180 top
R121  ev@243_4  [RC0402]  64.14 122.52 90 top
R122  ev@1.33k/f_4  [RC0402]  65.29 122.52 90 top
R123  ev@1.33k/f_4  [RC0402]  67.7 122.52 270 top
R124  *ev@short_4  [SHORT0402]  28.33 122.14 0 top
R125  *1k_4  [RC0402]  89.37 121.65 0 top
R126  *1k_4  [RC0402]  91.91 121.65 0 top
R127  *short_4  [SHORT0402]  94.83 121.52 0 top
R128  *short_8  [SHORT0805]  132.55 121.52 270 top
R129  49.9/f_4  [RC0402]  98.13 121.4 180 top
R130  tpl@100k_4  [RC0402]  148.68 121.4 180 top
R131  8.2k_4  [RC0402]  150.33 120.89 90 top
R132  *10k_4  [RC0402]  151.34 120.89 90 top
R133  *short_8  [SHORT0805]  135.72 120.63 0 top
R134  10k_4  [RC0402]  152.87 120.63 0 top
R135  *1k_4  [RC0402]  89.37 120.38 0 top
R136  *1k_4  [RC0402]  91.91 120.38 0 top
R137  *10k_4  [RC0402]  148.68 120.38 180 top
R138  10k_4  [RC0402]  154.9 120.25 180 top
R139  10k_4  [RC0402]  148.68 119.36 180 top
R140  *1k_4  [RC0402]  152.74 119.36 180 top
R141  10k_4  [RC0402]  150.71 119.24 0 top
R142  *1k_4  [RC0402]  89.37 119.11 0 top
R143  1k_4  [RC0402]  91.91 119.11 0 top
R144  *short_8  [SHORT0805]  129.75 119.11 90 top
R145  *short_6  [SHORT0603]  132.61 119.11 180 top
R146  8.2k_4  [RC0402]  154.77 119.11 0 top
R147  *ev@0_4  [RC0402]  23.96 118.6 0 top
R148  ev@10k/f_4  [RC0402]  26.12 118.6 0 top
R149  ev@51.1/f_4  [RC0402]  58 118.22 0 top
R150  51_4  [RC0402]  89.37 117.84 180 top
R151  51_4  [RC0402]  91.91 117.84 180 top
R152  51_4  [RC0402]  96.61 117.84 180 top
R153  *1k_4  [RC0402]  93.94 117.33 0 top
R154  *0_6  [RC0603]  150.83 117.2 90 top
R155  10k_4  [RC0402]  160.87 117.2 90 top
R156  10k_4  [RC0402]  161.88 117.2 90 top
R157  10k_4  [RC0402]  166.07 117.2 90 top
R158  10k_4  [RC0402]  162.9 117.2 90 top
R159  10k_4  [RC0402]  163.92 117.2 90 top
R160  10k_4  [RC0402]  165.06 117.2 90 top
R161  ev@42.2/f_4  [RC0402]  58 117.08 0 top
R162  *short_4  [SHORT0402]  89.37 116.75 0 top
R163  *ev@0_4  [RC0402]  33.23 116.7 180 top
R164  51_4  [RC0402]  91.53 116.7 0 top
R165  *short_8  [SHORT0805]  159.32 115.93 270 top
R166  *51_4  [RC0402]  87.31 115.96 90 top
R167  *evg@0_4  [RC0402]  33.23 115.68 0 top
R168  *short_6  [SHORT0603]  153.88 115.55 0 top
R169  ev@10k/f_4  [RC0402]  53.93 114.79 90 top
R170  *ev@10k/f_4  [RC0402]  55.08 114.79 90 top
R171  ev@10k/f_4  [RC0402]  56.22 114.79 90 top
R172  ev@40.2/f_4  [RC0402]  57.36 114.79 270 top
R173  *ev@60.4_4  [RC0402]  58.51 114.79 270 top
R174  *ev@60.4_4  [RC0402]  59.65 114.79 270 top
R175  ev@4.7k_4  [RC0402]  60.79 114.79 270 top
R176  ev@4.7k_4  [RC0402]  65.87 114.66 90 top
R177  ev@10k/f_4  [RC0402]  37.55 110.6 0 top
R178  *ev@0_4  [RC0402]  34.3 110.47 180 top
R179  ev@100k/f_4  [RC0402]  44.41 109.97 0 top
R180  *ev@10k/f_4  [RC0402]  35.9 109.84 90 top
R181  *ev@short_4  [SHORT0402]  37.55 109.46 180 top
R182  *evg@10k/f_4  [RC0402]  34.3 109.33 180 top
R183  *ev@short_4  [SHORT0402]  44.41 108.95 0 top
R184  *evg@0_4  [RC0402]  37.55 108.44 180 top
R185  ev@10k/f_4  [RC0402]  39.1 108.42 90 top
R186  *short_6  [SHORT0603]  56.85 107.81 90 top
R187  *tpl@10k_4  [RC0402]  74 107.68 90 top
R188  *tsi@0_4  [RC0402]  75.14 107.68 270 top
R189  *ev@0_4  [RC0402]  37.55 107.43 180 top
R190  10k_4  [RC0402]  63.33 107.43 0 top
R191  100k_4  [RC0402]  65.49 107.43 180 top
R192  10k_4  [RC0402]  63.33 106.28 0 top
R193  0_4  [RC0402]  65.49 106.28 0 top
R194  tpl@0_6  [RC0603]  67.9 106.16 90 top
R195  *short_4  [SHORT0402]  84.13 106.03 90 top
R196  *1k_4  [RC0402]  85.2 106.03 270 top
R197  ev@100k/f_4  [RC0402]  37.3 105.77 180 top
R198  100k_4  [RC0402]  159.02 105.77 0 top
R199  *ev@short_4  [SHORT0402]  43.39 105.65 180 top
R200  *short_6  [SHORT0603]  50.5 105.52 180 top
R201  *ev@0_4  [RC0402]  43.39 104.5 0 top
R202  10k_4  [RC0402]  146.14 104.38 0 top
R203  10k_4  [RC0402]  148.68 104.38 180 top
R204  10k_4  [RC0402]  153.37 104.38 270 top
R205  *short_6  [SHORT0603]  50.5 104.25 180 top
R206  10k_4  [RC0402]  158.2 104.12 0 top
R207  22.6/f_4  [RC0402]  140.67 104 270 top
R208  10k_4  [RC0402]  141.82 104 270 top
R209  10k_4  [RC0402]  142.96 104 270 top
R210  *short_6  [SHORT0603]  136.97 103.62 90 top
R211  *short_6  [SHORT0603]  138.13 103.62 90 top
R212  *0_6  [RC0603]  139.3 103.62 90 top
R213  *10k_4  [RC0402]  151.65 103.62 270 top
R214  10k_4  [RC0402]  148.68 103.36 0 top
R215  1k_4  [RC0402]  36.66 102.73 90 top
R216  100k_4  [RC0402]  42.63 102.73 90 top
R217  *short_4  [SHORT0402]  43.65 102.73 270 top
R218  *ev@short_4  [SHORT0402]  44.66 102.73 90 top
R219  10k_4  [RC0402]  144.74 102.22 90 top
R220  10k_4  [RC0402]  145.75 102.22 90 top
R221  *10k_4  [RC0402]  146.9 102.22 270 top
R222  22_4  [RC0402]  140.42 101.96 270 top
R223  22_4  [RC0402]  141.44 101.96 270 top
R224  tpm@22_4  [RC0402]  142.45 101.96 270 top
R225  10k_4  [RC0402]  143.72 101.96 270 top
R226  8.2k_4  [RC0402]  147.91 101.84 270 top
R227  *10k_4  [RC0402]  149.06 101.84 90 top
R228  *10k_4  [RC0402]  150.2 101.84 90 top
R229  *short_8  [SHORT0805]  47.01 100.94 90 top
R230  *tpl@0_6  [RC0603]  55.97 100.69 0 top
R231  10k_4  [RC0402]  151.6 100.69 270 top
R232  *short_8  [SHORT0805]  137.25 99.93 270 top
R233  10k_4  [RC0402]  143.72 99.93 270 top
R234  *10k_4  [RC0402]  144.74 99.93 90 top
R235  *10k_4  [RC0402]  145.75 99.93 90 top
R236  *short_4  [SHORT0402]  147.02 99.81 90 top
R237  *8.2k_4  [RC0402]  149.06 99.81 90 top
R238  1k_4  [RC0402]  150.2 99.81 90 top
R239  *short_4  [SHORT0402]  142.71 97.65 90 top
R240  *2.2k_4  [RC0402]  146.64 97.52 180 top
R241  4.7k_4  [RC0402]  152.23 95.49 180 top
R242  0_4  [RC0402]  144.23 95.36 90 top
R243  0_4  [RC0402]  147.79 94.34 270 top
R244  2.2k_4  [RC0402]  152.23 94.09 0 top
R245  4.7k_4  [RC0402]  196.81 94.09 90 top
R246  *0_4  [RC0402]  197.95 94.09 90 top
R247  2.49k/f_4  [RC0402]  220.94 93.71 270 top
R248  *0_4  [RC0402]  204.05 93.58 90 top
R249  *short_4  [SHORT0402]  232.37 93.58 180 top
R250  *0_4  [RC0402]  201.76 93.46 270 top
R251  4.7k_4  [RC0402]  203.03 93.46 90 top
R252  *0_4  [RC0402]  207.73 93.07 270 top
R253  *short_6  [SHORT0603]  211.79 93.07 90 top
R254  1k_4  [RC0402]  86.42 92.82 180 top
R255  2.2k_4  [RC0402]  152.23 92.82 0 top
R256  *short_4  [SHORT0402]  232.37 92.57 180 top
R257  4.7k_4  [RC0402]  149.5 92.18 180 top
R258  *0_4  [RC0402]  196.81 92.06 90 top
R259  0_4  [RC0402]  197.95 92.06 90 top
R260  *2.2k_4  [RC0402]  145.69 92.05 0 top
R261  *short_4  [SHORT0402]  86.39 91.65 180 top
R262  *0_6  [RC0603]  139.79 91.3 270 top
R263  *0_6  [RC0603]  141.06 91.3 90 top
R264  *0_6  [RC0603]  142.33 91.3 270 top
R265  4.7k_4  [RC0402]  201.76 91.3 90 top
R266  0_4  [RC0402]  203.03 91.3 90 top
R267  *0_4  [RC0402]  204.17 91.3 90 top
R268  *short_6  [SHORT0603]  94.25 91.16 90 top
R269  4.7k_4  [RC0402]  208.24 91.04 0 top
R270  *0_4  [RC0402]  227.77 90.81 0 top
R271  *1m_4  [RC0402]  224.88 90.92 0 top
R272  24.9/f_4  [RC0402]  95.65 90.91 90 top
R273  *short_6  [SHORT0603]  145.63 90.66 0 top
R274  *1k_4  [RC0402]  86.45 90.51 180 top
R275  *0_4  [RC0402]  227.77 89.8 0 top
R276  *short_4  [SHORT0402]  232.37 89.01 180 top
R277  *100k_4  [RC0402]  148.17 88.12 270 top
R278  *short_6  [SHORT0603]  150.96 88.12 270 top
R279  2/f_6  [RC0603]  94.76 88.11 180 top
R280  220k/f_4  [RC0402]  91.4 87.99 180 top
R281  *short_4  [SHORT0402]  232.37 87.99 180 top
R282  1.8k/f_4  [RC0402]  94.89 86.97 0 top
R283  1.8k/f_4  [RC0402]  94.89 84.56 180 top
R284  10k_4  [RC0402]  157.95 83.17 180 top
R285  *0_4  [RC0402]  223.48 83.17 180 top
R286  *short_6  [SHORT0603]  206.21 82.53 270 top
R287  10k_4  [RC0402]  223.48 80.88 180 top
R288  10k_4  [RC0402]  157.95 80.37 180 top
R289  *0_4  [RC0402]  31.33 78.98 180 top
R290  15k/f_4  [RC0402]  213.06 78.6 90 top
R291  *short_4  [SHORT0402]  217.64 78.6 270 top
R292  *short_6  [SHORT0603]  214.21 78.34 90 top
R293  1k_4  [RC0402]  213.06 76.56 90 top
R294  *short_4  [SHORT0402]  214.72 76.18 180 top
R295  1.5k/f_4  [RC0402]  217.64 76.18 90 top
R296  *short_4  [SHORT0402]  232.37 75.68 180 top
R297  *10k_4  [RC0402]  157.95 74.79 0 top
R298  43_4  [RC0402]  145.12 74.66 270 top
R299  4.7k_4  [RC0402]  146.77 74.66 270 top
R300  4.7k_4  [RC0402]  148.29 74.66 270 top
R301  4.7k_4  [RC0402]  149.56 74.66 90 top
R302  *short_4  [SHORT0402]  232.37 74.66 180 top
R303  *1k_4  [RC0402]  215.73 74.28 270 top
R304  24.9/f_4  [RC0402]  63.9 73.51 90 top
R305  *short_6  [SHORT0603]  62.54 71.74 90 top
R306  *10k_4  [RC0402]  209.13 71.74 90 top
R307  *short_4  [SHORT0402]  210.4 71.74 270 top
R308  *0_4  [RC0402]  212.05 71.74 270 top
R309  0_4  [RC0402]  213.32 71.74 270 top
R310  10k_4  [RC0402]  142.83 71.23 270 top
R311  *short_4  [SHORT0402]  232.37 71.1 180 top
R312  100k_4  [RC0402]  144.36 70.98 270 top
R313  4.7k_4  [RC0402]  149.56 70.98 270 top
R314  *10k_4  [RC0402]  150.96 70.98 270 top
R315  10k_4  [RC0402]  151.98 70.98 270 top
R316  *short_4  [SHORT0402]  152.99 70.98 90 top
R317  *short_4  [SHORT0402]  154.21 71 270 top
R318  10k_4  [RC0402]  226.15 70.98 0 top
R319  *short_6  [SHORT0603]  215.48 70.09 90 top
R320  *short_6  [SHORT0603]  216.87 70.09 90 top
R321  *short_4  [SHORT0402]  232.37 70.09 180 top
R322  5.1/f_6  [RC0603]  63.08 69.71 180 top
R323  *0_4  [RC0402]  140.55 69.58 0 top
R324  *0_8  [RC0805]  212.94 69.58 180 top
R325  1.8k/f_4  [RC0402]  63.33 68.56 0 top
R326  *short_4  [SHORT0402]  222.46 68.06 180 top
R327  1.8k/f_4  [RC0402]  63.33 67.55 180 top
R328  *0_4  [RC0402]  222.46 67.04 0 top
R329  *0_4  [RC0402]  226.91 65.77 270 top
R330  10k_4  [RC0402]  212.94 65.13 90 top
R331  47k_4  [RC0402]  232.5 64.63 90 top
R332  2.2_6  [RC0603]  136.85 63.74 0 top
R333  30/f_4  [RC0402]  64.6 63.48 180 top
R334  34.8/f_4  [RC0402]  125.05 62.82 0 top
R335  *100k_4  [RC0402]  130.79 62.98 90 top
R336  1k_4  [RC0402]  128 62.54 180 top
R337  2.2_6  [RC0603]  159.09 62.72 0 top
R338  100k_4  [RC0402]  214.59 62.47 0 top
R339  34.8/f_4  [RC0402]  62.32 62.34 180 top
R340  34.8/f_4  [RC0402]  64.47 62.34 180 top
R341  *100k_4  [RC0402]  132.8 62.26 0 top
R342  240/f_4  [RC0402]  92.92 62.21 0 top
R343  240/f_4  [RC0402]  125.05 61.66 0 top
R344  10k_4  [RC0402]  158.84 61.58 180 top
R345  34.8/f_4  [RC0402]  62.32 61.07 180 top
R346  34.8/f_4  [RC0402]  64.47 61.07 180 top
R347  100k_4  [RC0402]  158.84 60.56 180 top
R348  *22_4  [RC0402]  136.86 60.18 180 top
R349  *short_6  [SHORT0603]  132.67 59.83 90 top
R350  34.8/f_4  [RC0402]  62.32 59.8 180 top
R351  34.8/f_4  [RC0402]  64.47 59.8 180 top
R352  *short_4  [SHORT0402]  158.84 59.42 180 top
R353  100k_4  [RC0402]  136.36 58.66 90 top
R354  34.8/f_4  [RC0402]  62.32 58.53 180 top
R355  34.8/f_4  [RC0402]  64.47 58.53 180 top
R356  100k_4  [RC0402]  158.84 58.4 0 top
R357  24.9/f_4  [RC0402]  54.95 58.15 270 top
R358  *short_6  [SHORT0603]  58.25 57.77 180 top
R359  34.8/f_4  [RC0402]  62.32 57.39 180 top
R360  34.8/f_4  [RC0402]  64.47 57.39 180 top
R361  ev@10k_4  [RC0402]  158.84 57.39 180 top
R362  ev@10k_4  [RC0402]  136.86 57.13 0 top
R363  2/f_6  [RC0603]  58.25 56.37 180 top
R364  34.8/f_4  [RC0402]  64.47 56.12 180 top
R365  1.8k/f_4  [RC0402]  62.24 54.87 0 top
R366  1.8k/f_4  [RC0402]  64.47 54.85 0 top
R367  100k_4  [RC0402]  135.21 54.85 270 top
R368  34.8/f_4  [RC0402]  66.38 53.83 270 top
R369  34.8/f_4  [RC0402]  67.4 53.83 270 top
R370  34.8/f_4  [RC0402]  68.41 53.83 270 top
R371  34.8/f_4  [RC0402]  69.43 53.83 270 top
R372  34.8/f_4  [RC0402]  70.44 53.83 270 top
R373  34.8/f_4  [RC0402]  71.46 53.83 270 top
R374  240/f_4  [RC0402]  76.62 53.83 270 top
R375  470_4  [RC0402]  114 53.83 90 top
R376  *short_4  [SHORT0402]  115.02 53.83 90 top
R377  *short_4  [SHORT0402]  136.99 53.83 180 top
R378  240/f_4  [RC0402]  107.59 53.82 270 top
R379  10k_4  [RC0402]  136.99 52.82 0 top
R380  ev@10k_4  [RC0402]  158.84 52.82 180 top
R381  *0_4  [RC0402]  243.8 51.93 90 top
R382  *kbl@short_4  [SHORT0402]  71.84 51.29 90 top
R383  *short_4  [SHORT0402]  236.43 50.91 180 top
R384  *short_4  [SHORT0402]  84.54 49.77 270 top
R385  *short_4  [SHORT0402]  87.97 49.77 270 top
R386  10k_4  [RC0402]  89.11 49.77 270 top
R387  10k_4  [RC0402]  90.26 49.77 270 top
R388  *0_4  [RC0402]  91.4 49.77 270 top
R389  *short_4  [SHORT0402]  92.54 49.77 270 top
R390  *10k/f_4  [RC0402]  243.8 49.77 90 top
R391  *29.4k/f_4  [RC0402]  242.27 49.39 180 top
R392  *short_6  [SHORT0603]  238.34 48.62 270 top
R393  *short_6  [SHORT0603]  232.5 48.24 270 top
R394  bl@10k_4  [RC0402]  70.19 47.23 0 top
R395  *short_6  [SHORT0603]  229.96 47.23 270 top
R396  *short_4  [SHORT0402]  241.77 45.83 270 top
R397  *10k_4  [RC0402]  228.3 45.32 180 top
R398  *short_6  [SHORT0603]  226.91 43.16 270 top
R399  *4.7k_4  [RC0402]  157.44 42.78 90 top
R400  *100k/f_4  [RC0402]  155.79 42.4 0 top
R401  *4.7k_4  [RC0402]  145.5 42.15 0 top
R402  *4.7k_4  [RC0402]  155.79 41.13 180 top
R403  *0_4  [RC0402]  240.75 40.62 180 top
R404  *10k_4  [RC0402]  242.78 40.62 0 top
R405  33_4  [RC0402]  227.8 39.73 0 top
R406  0_4  [RC0402]  240.75 39.61 180 top
R407  *10k_4  [RC0402]  242.78 39.61 180 top
R408  *short_6  [SHORT0603]  226.53 37.32 180 top
R409  47k_4  [RC0402]  229.19 35.04 270 top
R410  39.2k/f_4  [RC0402]  232.5 34.02 90 top
R411  20k/f_4  [RC0402]  233.51 34.02 90 top
R412  4.7k_4  [RC0402]  229.32 32.88 270 top
R413  *0_4  [RC0402]  233.26 31.48 0 top
R414  *short_4  [SHORT0402]  234.4 30.34 180 top
R415  *short_4  [SHORT0402]  229.7 29.83 90 top
R416  *short_4  [SHORT0402]  230.72 29.83 90 top
R417  *short_4  [SHORT0402]  235.29 29.19 180 top
R418  56_4  [RC0402]  236.94 28.69 270 top
R419  56_4  [RC0402]  238.21 28.69 270 top
R420  1k_4  [RC0402]  240.75 27.67 90 top
R421  2.2k_4  [RC0402]  241.77 27.67 90 top
R422  *short_6  [SHORT0603]  236.94 26.27 90 top
R423  *short_6  [SHORT0603]  238.21 26.27 90 top
R424  22k/f_4  [RC0402]  241.26 26.15 0 top
R425  22k/f_4  [RC0402]  241.26 25.13 180 top
R426  *short_6  [SHORT0603]  233.64 18.4 90 top
R427  *short_4  [SHORT0402]  235.04 13.32 180 top
R428  0_6  [RC0603]  233.64 6.08 90 top
R429  0_6  [RC0603]  234.91 6.08 90 top
R430  0_6  [RC0603]  237.19 4.05 270 top
R431  0_6  [RC0603]  239.73 4.05 270 top
R432  300_4  [RC0402]  22.82 165.34 270 bottom
R433  680_4  [RC0402]  23.83 165.34 270 bottom
R434  *short_4  [SHORT0402]  150.58 164.19 0 bottom
R435  ev@100/f_4  [RC0402]  61.35 163.54 90 bottom
R436  ev@100/f_4  [RC0402]  62.37 163.54 270 bottom
R437  *ev@short_8  [SHORT0805]  11.52 163.43 0 bottom
R438  *short_4  [SHORT0402]  150.58 163.18 0 bottom
R439  *1m_4  [RC0402]  22.82 163.05 90 bottom
R440  *1m_4  [RC0402]  23.83 163.05 90 bottom
R441  ev@100/f_4  [RC0402]  59.27 162.29 270 bottom
R442  ev@100/f_4  [RC0402]  60.28 162.29 90 bottom
R443  ev@100/f_4  [RC0402]  61.35 161.38 270 bottom
R444  ev@100/f_4  [RC0402]  62.37 161.38 90 bottom
R445  ev@10k_4  [RC0402]  10.37 161.27 90 bottom
R446  ev@1k_4  [RC0402]  12.02 161.27 90 bottom
R447  ev@10k_4  [RC0402]  13.17 161.27 270 bottom
R448  2.2k_4  [RC0402]  108.42 161.27 90 bottom
R449  75_4  [RC0402]  149.82 160.64 90 bottom
R450  100/f_4  [RC0402]  73.49 160.51 180 bottom
R451  100/f_4  [RC0402]  75.9 160.51 180 bottom
R452  100/f_4  [RC0402]  78.32 160.51 180 bottom
R453  100/f_4  [RC0402]  80.86 160.51 180 bottom
R454  ev@100/f_4  [RC0402]  57.29 160.11 0 bottom
R455  75_4  [RC0402]  149.69 158.99 180 bottom
R456  ev@100/f_4  [RC0402]  57.29 158.97 0 bottom
R457  ev@100/f_4  [RC0402]  61.22 158.97 90 bottom
R458  ev@100/f_4  [RC0402]  62.37 158.97 270 bottom
R459  100/f_4  [RC0402]  102.57 158.23 90 bottom
R460  *short_4  [SHORT0402]  149.95 157.84 0 bottom
R461  ev@1.33k/f_4  [RC0402]  31 157.83 0 bottom
